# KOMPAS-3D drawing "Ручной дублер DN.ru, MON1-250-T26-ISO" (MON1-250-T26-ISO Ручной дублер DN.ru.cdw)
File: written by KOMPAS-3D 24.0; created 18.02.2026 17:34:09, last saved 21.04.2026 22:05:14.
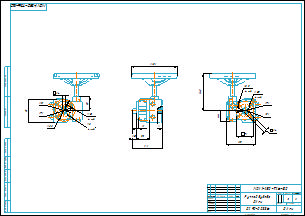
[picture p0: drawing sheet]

Document properties: Автор: R2D2; Форматы листов документа: A2; Полное имя файла: MON1-250-T26-ISO Ручной дублер DN.ru.m3d; Масса: 3; Наименование: Ручной дублер DN.ru; Количество листов документа: 1; Примечание: D290-00336

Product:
- Part/product: Ручной дублер DN.ru  | designation MON1-250-T26-ISO
    Масса: 3
    Раздел спецификации: Прочие изделия
    Примечание: D290-00336

Views: Вид 1, Спереди, Проекционный вид 2, Местный разрез 1, Проекционный вид 3
Referenced files in E:\Работа\Зайцев\Аксессуары для пневмоприводов\Ручной дублер DN.ru\MON1-250-T26-ISO Ручной дублер DN.ru\: MON1-250-T26-ISO Ручной дублер DN.ru.m3d
Referenced files in E:\Работа\Зайцев\Для компаса\: чертеж DN.ru А3.cdt
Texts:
  MON1-250-T26-ISO
  чертеж DN.ru А3.cdt
  Ручной дублер
  Ручной дублер DN.ru
  MON1-250-T26-ISO Ручной дублер DN.ru
Dimensions and other numbers on the sheet: 0; 3; 2; 4; 14; 50; 70; 6; 4 отв.; 8; 90; 55; 88; 22; 16; 120; 53; 10; 180; 5; 8,5; 6,5; 115; 44; 145; 1:2; 1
